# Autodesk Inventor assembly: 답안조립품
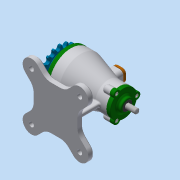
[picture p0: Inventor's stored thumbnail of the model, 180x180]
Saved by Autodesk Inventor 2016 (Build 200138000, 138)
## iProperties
Created: 2018-03
Part Number: 답안조립품
Material: 일반
Document SubType Name: Assembly
Designer: 605-03
Author: 605-03
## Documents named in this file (15)
- C:\Users\605-03\Desktop\480307V1009\답안조립품.iam
- C:\Users\605-03\Desktop\480307V1009\뒤커버.ipt
- C:\Users\605-03\Desktop\480307V1009\마개.ipt
- C:\Users\605-03\Desktop\480307V1009\베어링-6200.ipt
- C:\Users\605-03\Desktop\480307V1009\베어링-6203.ipt
- C:\Users\605-03\Desktop\480307V1009\본체.ipt
- C:\Users\605-03\Desktop\480307V1009\볼트 M4 x 12.ipt
- 볼트 M4 x 12.ipt
- C:\Users\605-03\Desktop\480307V1009\스프로킷.ipt
- C:\Users\605-03\Desktop\480307V1009\앞커버.ipt
- C:\Users\605-03\Desktop\480307V1009\오일 실 10 20 7.ipt
- C:\Users\605-03\Desktop\480307V1009\오일 실 17 30 8.ipt
- C:\Users\605-03\Desktop\480307V1009\축.ipt
- C:\Users\605-03\Desktop\480307V1009\키 5 x 5.ipt
- 키 5 x 5.ipt
